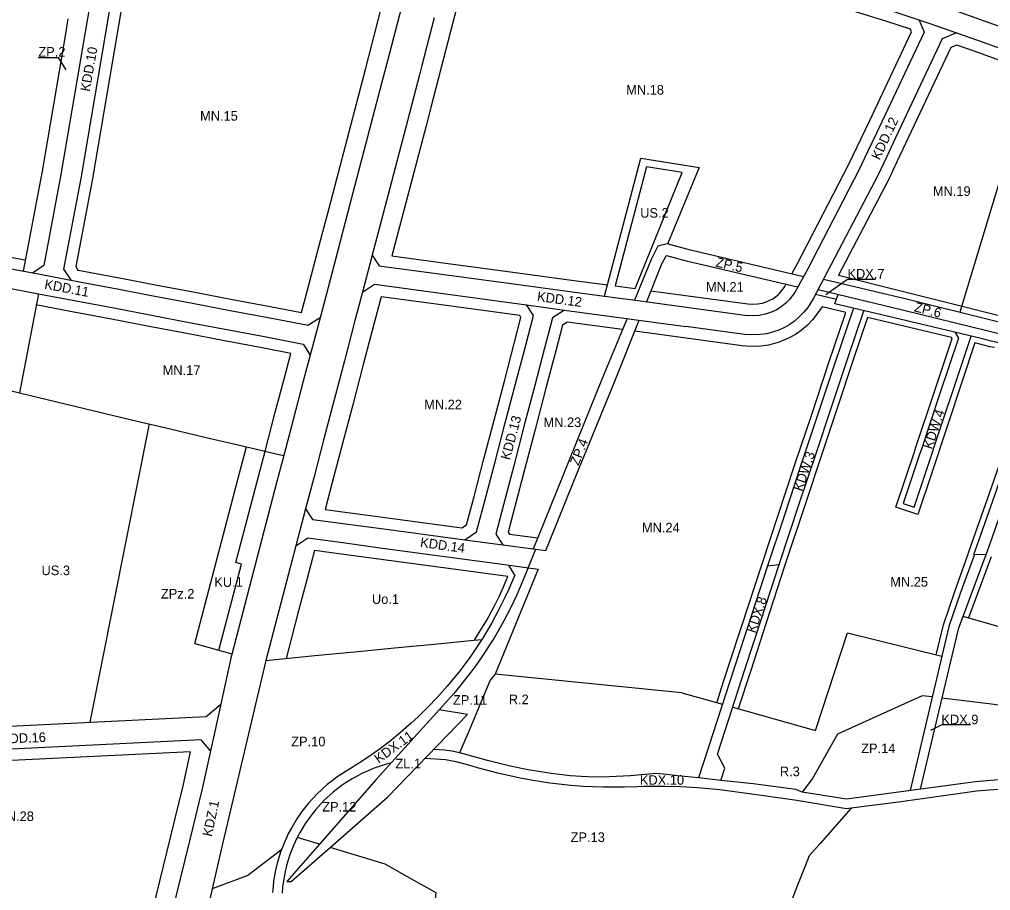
# Model space of a CAD drawing. Extents: x 7416945 to 7418410, y 5548550 to 5549803.
# Drawn here: x 7417372 to 7417879, y 5548828 to 5549282 of the extents above; entities that cross this region are included whole.
import ezdxf

# ---------------------------------------------------------------- set-up
doc = ezdxf.new("R2010")
doc.units = 0
for name, color, linetype in [('linie rozgraniczające', 7, 'Continuous'), ('nieprzekraczalna linia lokalizacyjna', 7, 'Continuous'), ('nieprzekraczalne linie zabudowy', 7, 'Continuous'), ('przeznaczenia terenów', 7, 'Continuous')]:
    doc.layers.add(name, color=color, linetype=linetype)

msp = doc.modelspace()

# ---------------------------------------------------------------- linework, layer by layer
at = {"layer": 'linie rozgraniczające'}
for p, q in [((7417384.22, 5549148.78), (7417364.57, 5549152.5)), ((7417362.71, 5549142.67), (7417382.36, 5549138.96)), ((7417443.16, 5549137.57), (7417423.51, 5549141.29)), ((7417382.36, 5549138.96), (7417372.55, 5549087.23)), ((7417382.36, 5549138.96), (7417402, 5549135.23)), ((7417402, 5549135.23), (7417421.66, 5549131.51)), ((7417462.81, 5549133.84), (7417443.16, 5549137.57)), ((7417482.45, 5549130.09), (7417462.81, 5549133.84)), ((7417502.11, 5549126.37), (7417482.45, 5549130.09)), ((7417523.03, 5549122.41), (7417502.11, 5549126.37)), ((7417529.21, 5549126.31), (7417524.25, 5549123.18)), ((7417460.94, 5549124.01), (7417480.6, 5549120.29)), ((7417480.6, 5549120.29), (7417500.25, 5549116.55)), ((7417524.25, 5549123.18), (7417523.03, 5549122.41)), ((7417500.25, 5549116.55), (7417520.47, 5549112.72)), ((7417520.47, 5549112.72), (7417521.18, 5549111.59)), ((7417440.08, 5549071.07), (7417409.24, 5548915.47)), ((7417637.81, 5548996.07), (7417641.77, 5549005.68)), ((7417643, 5548995.38), (7417620.54, 5548940.54)), ((7417630.78, 5548992.14), (7417627.73, 5548997.43)), ((7417762.54, 5548997.11), (7417768.63, 5548997.71)), ((7417864.45, 5548970.75), (7417980.26, 5548937.76)), ((7417787.49, 5548911.18), (7417804.25, 5548962.09)), ((7417804.25, 5548962.09), (7417853.48, 5548949.9)), ((7417463.99, 5548956.53), (7417483.27, 5548951.15)), ((7417717.79, 5548930.82), (7417620.54, 5548940.54)), ((7417717.79, 5548930.82), (7417739, 5548924.85)), ((7417744.4, 5548923.32), (7417787.49, 5548911.18)), ((7417528.9, 5548851.83), (7417511.9, 5548832.43)), ((7417528.9, 5548851.83), (7417517.33, 5548855.35))]:
    msp.add_line(p, q, dxfattribs=at)
for points in [[(7417600.38, 5549448.11), (7417591.9, 5549387.48), (7417586.15, 5549346.84), (7417584.38, 5549338.73), (7417582.4, 5549329.52), (7417581.1, 5549324.69), (7417570.58, 5549284.41), (7417563.36, 5549256.41)], [(7417420.61, 5549356.86), (7417394.15, 5549201.15), (7417385.15, 5549153.69), (7417379.31, 5549149.71)], [(7417433.7, 5549351.23), (7417429.92, 5549349.03), (7417404.45, 5549199.09), (7417395.47, 5549151.72), (7417399.45, 5549145.87)], [(7417906.81, 5549269.9), (7417851.87, 5549289.57), (7417833.76, 5549295.49), (7417808.87, 5549303.3), (7417795.71, 5549307.92), (7417790.77, 5549308.7), (7417775.81, 5549311.08), (7417756.77, 5549314.1), (7417742.03, 5549316.43), (7417726.22, 5549318.94), (7417710.69, 5549321.4), (7417699, 5549323.26), (7417679.25, 5549326.39), (7417661.44, 5549329.21), (7417642.3, 5549332.24), (7417632.4, 5549333.81), (7417607.94, 5549338.37), (7417603.72, 5549342.84)], [(7418147.34, 5549179.74), (7418143.99, 5549186.16), (7418084.45, 5549204.38), (7418040.68, 5549217.77), (7417983.92, 5549235), (7417952.55, 5549244.38), (7417903.8, 5549259.73), (7417872.26, 5549271.01), (7417847.4, 5549279.75), (7417826.56, 5549286.64), (7417807.47, 5549292.63), (7417790.03, 5549298.09), (7417775.67, 5549301.04), (7417764.12, 5549302.87), (7417752.53, 5549304.72), (7417740.93, 5549306.55), (7417719.26, 5549309.98), (7417700.5, 5549312.94), (7417681.74, 5549315.91), (7417662.97, 5549318.89), (7417638.22, 5549322.81), (7417619.42, 5549325.79), (7417605.57, 5549327.98), (7417599.85, 5549325.25)], [(7417397.8, 5549282.3), (7417396.12, 5549272.43), (7417384.31, 5549202.92), (7417374.39, 5549150.64)], [(7417588.8, 5549282.89), (7417582.37, 5549257.96), (7417581.11, 5549253.1), (7417574.91, 5549229.02), (7417565.67, 5549194.03), (7417556.43, 5549159.04), (7417551.32, 5549139.7), (7417547.25, 5549124.23), (7417541.92, 5549103.92), (7417536.6, 5549083.61), (7417531.27, 5549063.29), (7417525.95, 5549042.97), (7417521.69, 5549026.77), (7417516.61, 5549007.43), (7417512.79, 5548992.92), (7417507.71, 5548973.58), (7417500.89, 5548947.67), (7417492.57, 5548912.33), (7417478.58, 5548852.79), (7417472.9, 5548828.6), (7417470.41, 5548817.08)], [(7417841.59, 5549281.68), (7417844.21, 5549275.29), (7417819.3, 5549222.63), (7417814.75, 5549213.02)], [(7417861.02, 5549274.97), (7417853.66, 5549271.91), (7417829.26, 5549220.17), (7417824.74, 5549210.57)], [(7417902.54, 5549260.18), (7417862.8, 5549129.35)], [(7417563.36, 5549256.41), (7417562.35, 5549252.52), (7417543.61, 5549180.99), (7417538.49, 5549161.56), (7417533.39, 5549142.16), (7417529.21, 5549126.31), (7417524.1, 5549106.95), (7417520.51, 5549093.27), (7417515.4, 5549073.92), (7417510.3, 5549054.58), (7417506.75, 5549041.01), (7417483.36, 5548951.55), (7417482.77, 5548948.86), (7417475.23, 5548914.72), (7417474.34, 5548910.67), (7417467.59, 5548880.07), (7417461.13, 5548853.66), (7417451.56, 5548814.61)], [(7417814.75, 5549213.02), (7417810.21, 5549203.41), (7417783.5, 5549151.85), (7417776.71, 5549139.64), (7417775.64, 5549137.99), (7417773.81, 5549135.71), (7417772.09, 5549133.98), (7417770.41, 5549132.57), (7417768.52, 5549131.26), (7417766.99, 5549130.37), (7417765.02, 5549129.43), (7417761.52, 5549128.24), (7417758.27, 5549127.62), (7417754.82, 5549127.44), (7417751.89, 5549127.66)], [(7417677.49, 5549137.69), (7417696.49, 5549209.65), (7417723.78, 5549205.3), (7417726.83, 5549204.82)], [(7417824.74, 5549210.57), (7417820.21, 5549200.98), (7417786.44, 5549136.31), (7417784.99, 5549134.01), (7417783.52, 5549131.82), (7417781.44, 5549129.24), (7417779.28, 5549127), (7417776.37, 5549124.54), (7417773.86, 5549122.8), (7417771.38, 5549121.38), (7417768.44, 5549120.02), (7417766.23, 5549119.21), (7417763.95, 5549118.54), (7417761.96, 5549118.09), (7417758.66, 5549117.6), (7417753.88, 5549117.46), (7417750.55, 5549117.75), (7417745.51, 5549118.4), (7417719.92, 5549121.87)], [(7417726.83, 5549204.82), (7417710.38, 5549164.86)], [(7417781.26, 5549147.82), (7417722.44, 5549161.63), (7417710.2, 5549164.91), (7417705.42, 5549163.81), (7417701.83, 5549156.79), (7417693.26, 5549135.56)], [(7417556.43, 5549159.04), (7417560.1, 5549153.54), (7417592.59, 5549149.16), (7417612.06, 5549146.53), (7417631.54, 5549143.89), (7417659.51, 5549140.13), (7417677.49, 5549137.69), (7417694.99, 5549135.33), (7417751.89, 5549127.66)], [(7417778.23, 5549142.37), (7417720.98, 5549155.81), (7417710.09, 5549158.73), (7417709.49, 5549158.59), (7417707.29, 5549154.3), (7417699.39, 5549134.74)], [(7417423.51, 5549141.29), (7417403.87, 5549145.03), (7417384.22, 5549148.78)], [(7417791.78, 5549146.54), (7417835.03, 5549136.21), (7417879.03, 5549125.34), (7417899.92, 5549120.14), (7417910.43, 5549117.51)], [(7417551.32, 5549139.7), (7417557.55, 5549143.87), (7417597.18, 5549138.5), (7417636.81, 5549133.12), (7417656.64, 5549130.44), (7417719.92, 5549121.87)], [(7417788.92, 5549141.06), (7417833.61, 5549130.38), (7417877.58, 5549119.52), (7417898.47, 5549114.32), (7417914.41, 5549110.33), (7417943.45, 5549103.3), (7417969.7, 5549096.76), (7417975.19, 5549095.35), (7418012.94, 5549086.32), (7418038.97, 5549081.43), (7418066.78, 5549078.66), (7418089.62, 5549077.64), (7418100.12, 5549081.56)], [(7417798.48, 5549135.9), (7417787.63, 5549138.59)], [(7418054.47, 5549073.19), (7418030.76, 5549077.77), (7418012.99, 5549081.92), (7418002.38, 5549084.6), (7417984.13, 5549088.95), (7417978.23, 5549090.35), (7417967.59, 5549092.55), (7417941.97, 5549099.12), (7417902.4, 5549108.1), (7417892.31, 5549110.78), (7417881.65, 5549113.74), (7417879.1, 5549114.2), (7417874, 5549115.6), (7417870.28, 5549116.48), (7417838.19, 5549124.07), (7417797.73, 5549133.64), (7417799.37, 5549138.56)], [(7417421.66, 5549131.51), (7417441.3, 5549127.75), (7417460.94, 5549124.01)], [(7417604.68, 5549010.56), (7417610.89, 5549014.73), (7417615.15, 5549030.94), (7417620.48, 5549051.25), (7417625.8, 5549071.56), (7417631.13, 5549091.88), (7417636.45, 5549112.19), (7417640.5, 5549127.62), (7417636.81, 5549133.12)], [(7417656.64, 5549130.44), (7417650.41, 5549126.28), (7417646.3, 5549110.63), (7417641.2, 5549091.13), (7417635.57, 5549069.69), (7417630.21, 5549049.23), (7417624.83, 5549028.76), (7417620.82, 5549013.47), (7417624.51, 5549007.95)], [(7417807.36, 5549131.36), (7417797.45, 5549102.13), (7417788.66, 5549075.56), (7417779.73, 5549049.01), (7417771.03, 5549022.44), (7417762.54, 5548997.11), (7417752.05, 5548964.9), (7417750.49, 5548960.16), (7417742.71, 5548936.24), (7417734.17, 5548910.03), (7417726.5, 5548886.43)], [(7417738.22, 5548885.17), (7417740.29, 5548891.52), (7417736.41, 5548898.78), (7417742.39, 5548917.13), (7417750.78, 5548942.92), (7417759.08, 5548968.32), (7417768.63, 5548997.71), (7417779.29, 5549029.94), (7417787.7, 5549055.16), (7417796.02, 5549080.27), (7417804.38, 5549105.4), (7417812.71, 5549130.1)], [(7417689.32, 5549126.01), (7417676.42, 5549094.65), (7417655.91, 5549043.98), (7417643.05, 5549012.22), (7417640.42, 5549005.86)], [(7417646.95, 5549005), (7417648.87, 5549009.69), (7417661.64, 5549041.14), (7417682.54, 5549092.52), (7417695.59, 5549125.17)], [(7417251.28, 5549116.27), (7417275.19, 5549110.54), (7417294.67, 5549105.88), (7417314.13, 5549101.21), (7417333.61, 5549096.55), (7417353.08, 5549091.88), (7417372.55, 5549087.23), (7417392.02, 5549082.56), (7417411.49, 5549077.9), (7417430.97, 5549073.25), (7417450.44, 5549068.58), (7417469.91, 5549063.92), (7417489.41, 5549059.41), (7417506.4, 5549055.48), (7417510.3, 5549054.58)], [(7417860.47, 5549118.8), (7417862.06, 5549115.83), (7417852.26, 5549086.42), (7417842.79, 5549057.95), (7417842.01, 5549055.58), (7417833.32, 5549029.49), (7417839.01, 5549027.6), (7417845.12, 5549045.96), (7417853.34, 5549070.61), (7417861.22, 5549094.32), (7417868.73, 5549116.85)], [(7417521.18, 5549111.59), (7417524.1, 5549106.95)], [(7417917.65, 5549104.64), (7417911.1, 5549101.73), (7417901.89, 5549075.42), (7417890.76, 5549043.69), (7417878.59, 5549008.99), (7417876.3, 5549002.8), (7417870.46, 5549002.86), (7417870.18, 5549002.86), (7417872.8, 5549010.27), (7417881.05, 5549033.88), (7417890.12, 5549059.83), (7417897.87, 5549082.02), (7417905.29, 5549103.25), (7417902.77, 5549108.02)], [(7417473.15, 5548991.58), (7417487.4, 5549046.07), (7417488.27, 5549049.41), (7417488.25, 5549049.41), (7417490.8, 5549059.09)], [(7417521.69, 5549026.77), (7417525.38, 5549021.26), (7417565.03, 5549015.92), (7417604.68, 5549010.56), (7417624.51, 5549007.95), (7417640.42, 5549005.86), (7417641.77, 5549005.68), (7417646.95, 5549005)], [(7417516.61, 5549007.43), (7417522.84, 5549011.59), (7417542.35, 5549008.96), (7417561.83, 5549006.33), (7417581.33, 5549003.7), (7417600.81, 5549001.07), (7417620.29, 5548998.43), (7417643, 5548995.38)], [(7417870.46, 5549002.86), (7417862.99, 5548982.64), (7417857.16, 5548965.46), (7417836.92, 5548879.84)], [(7417876.3, 5549002.8), (7417861.96, 5548964.01), (7417842.23, 5548880.56)], [(7417637.81, 5548996.07), (7417634.66, 5548988.5), (7417631.83, 5548981.98), (7417628.67, 5548975.32), (7417625.03, 5548968.3), (7417622.47, 5548963.71), (7417619.81, 5548959.21), (7417617.47, 5548955.44), (7417615.03, 5548951.69), (7417612.53, 5548948.02), (7417610.39, 5548945), (7417607.91, 5548941.62), (7417604.62, 5548937.37), (7417602.17, 5548934.33), (7417598.97, 5548930.52), (7417594.79, 5548925.81), (7417591.35, 5548921.97)], [(7417463.99, 5548956.53), (7417473.15, 5548991.58)], [(7417630.78, 5548992.14), (7417629.08, 5548988.15), (7417627.63, 5548984.83), (7417625.61, 5548980.45), (7417622.67, 5548974.53), (7417618.75, 5548967.28), (7417613.93, 5548959.2), (7417613.59, 5548958.7), (7417607.31, 5548949.29), (7417602.28, 5548942.49), (7417595.58, 5548934.24), (7417590.35, 5548928.36), (7417585.52, 5548923.3), (7417580.32, 5548918.21), (7417576.78, 5548914.94), (7417571.24, 5548910.11), (7417565.78, 5548905.66), (7417560.69, 5548901.79), (7417556, 5548898.43), (7417552.26, 5548895.89), (7417549.88, 5548894.33), (7417547.52, 5548892.83), (7417546.53, 5548892.21), (7417546.03, 5548891.9), (7417542.29, 5548889.64), (7417540.4, 5548888.44), (7417537.93, 5548886.75), (7417535.49, 5548884.94), (7417532.96, 5548882.92), (7417530.16, 5548880.46), (7417527.71, 5548878.12), (7417523.25, 5548873.28), (7417519.8, 5548868.91), (7417517.13, 5548865.03), (7417514.49, 5548860.65), (7417512.86, 5548857.58), (7417510.8, 5548853.19), (7417508.65, 5548847.65), (7417506.94, 5548842.01), (7417505.89, 5548837.53), (7417505.03, 5548832.51), (7417504.73, 5548830.04), (7417504.44, 5548826.63)], [(7417500.89, 5548947.67), (7417526.52, 5548950.19), (7417547.27, 5548952.21), (7417568, 5548954.24), (7417588.75, 5548956.26), (7417599.01, 5548957.27), (7417609.49, 5548958.3), (7417613.59, 5548958.7)], [(7417620.54, 5548940.54), (7417617.96, 5548937.38), (7417613.08, 5548925.82), (7417606.94, 5548911.17), (7417602.03, 5548899.53)], [(7417848.46, 5548928.64), (7417843.25, 5548929.28), (7417837.74, 5548926.79), (7417799.12, 5548909.3), (7417786.05, 5548886.15), (7417780.56, 5548879)], [(7417946.22, 5548898.97), (7417942.6, 5548900.22), (7417922.04, 5548910.15), (7417889.72, 5548923.38), (7417879.42, 5548924.96), (7417863.45, 5548926.86), (7417853.47, 5548928.11)], [(7417273.67, 5548893.56), (7417278.95, 5548903.58), (7417288.09, 5548909.49), (7417371.16, 5548913.6), (7417469.91, 5548918.46), (7417477.47, 5548924.85)], [(7417534.44, 5548850.15), (7417564.62, 5548876.51), (7417606.08, 5548919.47), (7417591.35, 5548921.97), (7417558.57, 5548885.67), (7417528.9, 5548851.83)], [(7417472.11, 5548900.55), (7417467.24, 5548906.31), (7417371.76, 5548901.6), (7417296.55, 5548897.89)], [(7417885.15, 5548885.64), (7417870.98, 5548884.47), (7417803.72, 5548875.33), (7417780.56, 5548879), (7417777.4, 5548880.44), (7417755, 5548883.36), (7417738.22, 5548885.17), (7417726.58, 5548886.42), (7417715.7, 5548887.6), (7417710.08, 5548888.21), (7417704.57, 5548888.8), (7417690.88, 5548887.46), (7417680.06, 5548887.01), (7417671.53, 5548886.89), (7417668.68, 5548886.93), (7417665.47, 5548887.13), (7417659.67, 5548887.59), (7417649.74, 5548888.68), (7417637.82, 5548890.57), (7417628.34, 5548892.55), (7417616.53, 5548895.48), (7417607.24, 5548898.14), (7417601.27, 5548899.73), (7417597.88, 5548900.33), (7417594.06, 5548900.88), (7417588.5, 5548901.25)], [(7417547.13, 5548886.73), (7417551.61, 5548889.06), (7417554.41, 5548890.34), (7417557.7, 5548891.68), (7417560.82, 5548892.78), (7417564.12, 5548893.79), (7417566.45, 5548894.4)], [(7417806.23, 5548870.62), (7417803.67, 5548870.28), (7417777.91, 5548874.72), (7417759.34, 5548877.34), (7417737.68, 5548880.2), (7417726.01, 5548881.27), (7417717.38, 5548881.76), (7417709.21, 5548882), (7417706.51, 5548882.03), (7417702.57, 5548882.03), (7417698.08, 5548881.97), (7417694.58, 5548881.87), (7417688, 5548881.65), (7417681.8, 5548881.57), (7417677.06, 5548881.61), (7417671.25, 5548881.79), (7417666.67, 5548882.03), (7417660.06, 5548882.52), (7417649.1, 5548883.72), (7417640.32, 5548885.04), (7417633.5, 5548886.28), (7417621.99, 5548888.83), (7417611.27, 5548891.72), (7417606.79, 5548893.09), (7417600.19, 5548894.84), (7417594.69, 5548895.82), (7417583.96, 5548896.55)], [(7417547.13, 5548886.73), (7417545.94, 5548886.01), (7417544.17, 5548884.92), (7417542.78, 5548884.02), (7417540.84, 5548882.68), (7417536.18, 5548879.09), (7417531.25, 5548874.58), (7417527.06, 5548870.03), (7417523.83, 5548865.94), (7417521.33, 5548862.32), (7417518.84, 5548858.19), (7417517.33, 5548855.35), (7417515.4, 5548851.23), (7417513.38, 5548846.01), (7417511.77, 5548840.72), (7417510.79, 5548836.54), (7417509.98, 5548831.79), (7417509.71, 5548829.52), (7417509.44, 5548826.38)], [(7417885.14, 5548880.62), (7417871.53, 5548879.5), (7417844.5, 5548875.74), (7417834.49, 5548874.34), (7417832.16, 5548874.04), (7417806.23, 5548870.62), (7417789.92, 5548852.15), (7417784.27, 5548845.73), (7417782.74, 5548841.85), (7417778.25, 5548830.48), (7417768.76, 5548806.39)], [(7417509.23, 5548849.13), (7417491.62, 5548835.61), (7417472.9, 5548828.6)], [(7417511.9, 5548832.43), (7417514.18, 5548832.45), (7417534.44, 5548850.15)], [(7417570.23, 5548837.5), (7417567.57, 5548838.96), (7417563.23, 5548841.38), (7417534.44, 5548850.15)], [(7417570.23, 5548837.5), (7417589.55, 5548826.76), (7417587.91, 5548810.29), (7417584.76, 5548804.15), (7417543.15, 5548756.83), (7417539.16, 5548752.01), (7417525.02, 5548734.98), (7417512.78, 5548718.47)]]:
    msp.add_lwpolyline(points, dxfattribs=at)
at = {"layer": 'nieprzekraczalna linia lokalizacyjna'}
msp.add_lwpolyline([(7417683.03, 5549143), (7417693.53, 5549141.58), (7417718, 5549202.17), (7417699.43, 5549205.13), (7417683.03, 5549143)], dxfattribs=at)
at = {"layer": 'nieprzekraczalne linie zabudowy'}
for points in [[(7417434.88, 5549342.36), (7417410.35, 5549198.03), (7417401.82, 5549153.05), (7417403.01, 5549151.3), (7417404.99, 5549150.92), (7417424.63, 5549147.18), (7417444.28, 5549143.47), (7417463.93, 5549139.73), (7417483.57, 5549135.98), (7417503.23, 5549132.27), (7417519.62, 5549129.16), (7417523.72, 5549144.71), (7417528.82, 5549164.11), (7417533.94, 5549183.53), (7417553.08, 5549256.59), (7417560.91, 5549286.92), (7417570.83, 5549324.94), (7417562.97, 5549325.95), (7417544.48, 5549328.32), (7417525.98, 5549330.69), (7417507.49, 5549333.06), (7417487.5, 5549335.62), (7417434.88, 5549342.36)], [(7417609.16, 5549321.34), (7417598.48, 5549280.38), (7417587.05, 5549236.07), (7417584.59, 5549226.5), (7417566.68, 5549158.71), (7417593.39, 5549155.11), (7417612.86, 5549152.48), (7417632.34, 5549149.84), (7417660.31, 5549146.08), (7417679.03, 5549143.54)], [(7417280.75, 5549300.59), (7417278.75, 5549283.32), (7417276.73, 5549271.22), (7417267.63, 5549218.08), (7417264.16, 5549195.55), (7417262.15, 5549179.79), (7417263.67, 5549177.71), (7417287.09, 5549173.26), (7417326.39, 5549165.83), (7417346.03, 5549162.1), (7417365.68, 5549158.4), (7417375.51, 5549156.54)], [(7417775.19, 5549149.25), (7417778.21, 5549154.69), (7417804.83, 5549206.07), (7417809.33, 5549215.58), (7417815.66, 5549228.96), (7417837.66, 5549275.46), (7417837.09, 5549276.84), (7417824.72, 5549280.93), (7417805.68, 5549286.9)], [(7417799.6, 5549148.55), (7417830.66, 5549140.78), (7417908.42, 5549121.35), (7417923.1, 5549171.81), (7417929.47, 5549193.7), (7417939.89, 5549229.5), (7417923.27, 5549234.73), (7417926.71, 5549246.23), (7417901.89, 5549254.04), (7417870.25, 5549265.36), (7417861.19, 5549268.54), (7417858.1, 5549267.26), (7417830.16, 5549208.01), (7417825.59, 5549198.31), (7417799.6, 5549148.55)], [(7417701.71, 5549140.47), (7417752.34, 5549133.64), (7417754.89, 5549133.45), (7417757.55, 5549133.59), (7417759.99, 5549134.05), (7417762.75, 5549134.99), (7417764.19, 5549135.68), (7417765.3, 5549136.33), (7417766.77, 5549137.35), (7417768.03, 5549138.4), (7417769.33, 5549139.71), (7417770.77, 5549141.51), (7417771.56, 5549142.74), (7417772.15, 5549143.8)], [(7417561.04, 5549137.34), (7417556.92, 5549121.69), (7417551.59, 5549101.38), (7417546.27, 5549081.07), (7417540.94, 5549060.76), (7417535.62, 5549040.43), (7417531.94, 5549026.43), (7417565.83, 5549021.87), (7417603.23, 5549016.81), (7417605.66, 5549018.45), (7417609.35, 5549032.46), (7417614.68, 5549052.77), (7417620, 5549073.08), (7417625.33, 5549093.4), (7417630.65, 5549113.71), (7417634.01, 5549126.53), (7417633.33, 5549127.54), (7417596.37, 5549132.55), (7417561.04, 5549137.34)], [(7417476.53, 5548953.08), (7417488.27, 5548997.99), (7417485.36, 5548998.74), (7417497.08, 5549043.54), (7417500.55, 5549056.83), (7417500.55, 5549056.83), (7417505.73, 5549076.47), (7417510.84, 5549095.82), (7417513.99, 5549107.84), (7417499.13, 5549110.66), (7417479.48, 5549114.4), (7417459.82, 5549118.12), (7417440.17, 5549121.86), (7417420.54, 5549125.62), (7417400.88, 5549129.33), (7417381.07, 5549133.1)], [(7417736.11, 5548925.66), (7417739.86, 5548937.17), (7417747.64, 5548961.09), (7417749.2, 5548965.83), (7417759.69, 5548998.05), (7417768.18, 5549023.38), (7417776.88, 5549049.95), (7417785.81, 5549076.51), (7417794.61, 5549103.08), (7417803.46, 5549129.2), (7417790.97, 5549132.16), (7417788.35, 5549128.26), (7417785.94, 5549125.26), (7417783.38, 5549122.62), (7417780.02, 5549119.77), (7417777.06, 5549117.73), (7417774.14, 5549116.05), (7417770.75, 5549114.48), (7417768.12, 5549113.51), (7417765.46, 5549112.73), (7417763.06, 5549112.18), (7417759.18, 5549111.61), (7417753.72, 5549111.45), (7417749.35, 5549111.83), (7417693.29, 5549119.42)], [(7417880.98, 5549110.81), (7417878.44, 5549111.27), (7417873.26, 5549112.69), (7417870.71, 5549113.3), (7417864.07, 5549093.37), (7417856.19, 5549069.66), (7417847.97, 5549045.01), (7417840.91, 5549023.81), (7417829.52, 5549027.59), (7417839.16, 5549056.52), (7417839.94, 5549058.89), (7417849.41, 5549087.37), (7417858.81, 5549115.55), (7417858.47, 5549116.19), (7417814.68, 5549126.55), (7417807.22, 5549104.45), (7417798.87, 5549079.32), (7417790.55, 5549054.21), (7417782.14, 5549028.99), (7417771.48, 5548996.78), (7417761.93, 5548967.39), (7417753.63, 5548941.99), (7417747.29, 5548922.51)], [(7417686.96, 5549120.28), (7417658.08, 5549124.19), (7417655.64, 5549122.55), (7417652.1, 5549109.11), (7417647, 5549089.61), (7417641.37, 5549068.17), (7417636.01, 5549047.71), (7417630.63, 5549027.24), (7417627.31, 5549014.56), (7417627.99, 5549013.54), (7417642.79, 5549011.6)], [(7417850.57, 5548950.62), (7417854.28, 5548966.29), (7417860.16, 5548983.64), (7417865.94, 5548999.86), (7417869.97, 5549011.26), (7417878.22, 5549034.87), (7417887.29, 5549060.82)], [(7417609.73, 5548958.32), (7417611.39, 5548960.8), (7417616.14, 5548968.77), (7417620, 5548975.91), (7417622.9, 5548981.75), (7417624.9, 5548986.06), (7417626.33, 5548989.33), (7417627.22, 5548991.44), (7417600.01, 5548995.12), (7417580.53, 5548997.75), (7417561.03, 5549000.38), (7417541.55, 5549003.01), (7417526.33, 5549005.07), (7417522.46, 5548990.38), (7417517.38, 5548971.04), (7417511.51, 5548948.71)], [(7417879.11, 5549001.76), (7417867.35, 5548969.92)], [(7417441.31, 5548814.81), (7417441.85, 5548816.99), (7417451.42, 5548856.04), (7417457.85, 5548882.34), (7417461.75, 5548900.04), (7417372.05, 5548895.61), (7417298.16, 5548891.96), (7417293.26, 5548889.42), (7417290.97, 5548884.14), (7417292.69, 5548828.47), (7417292.73, 5548826.87), (7417301.25, 5548827.4), (7417301.53, 5548818.39)]]:
    msp.add_lwpolyline(points, dxfattribs=at)
at = {"layer": 'przeznaczenia terenów'}
for points in [[(7417382.32, 5549262.13), (7417392.75, 5549262.13), (7417396.69, 5549255.68)], [(7417818.77, 5549146.43), (7417804.24, 5549146.43), (7417793.04, 5549138.42)], [(7417868.43, 5548914.08), (7417853.43, 5548914.08), (7417847.49, 5548911.08)]]:
    msp.add_lwpolyline(points, dxfattribs=at)

# ---------------------------------------------------------------- texts
for s, p in [('ZP.2', (7417382.36, 5549262.6)), ('MN.18', (7417688.86, 5549242.8)), ('MN.15', (7417466.68, 5549229.19)), ('MN.19', (7417848.75, 5549189.94)), ('US.2', (7417696.16, 5549178.59)), ('KDX.7', (7417804.23, 5549146.87)), ('MN.21', (7417730.47, 5549139.99)), ('MN.17', (7417447.17, 5549096.53)), ('MN.22', (7417583.53, 5549078.67)), ('MN.23', (7417645.72, 5549069.39)), ('MN.24', (7417697.08, 5549014.46)), ('US.3', (7417384, 5548992.18)), ('KU.1', (7417474.09, 5548986.09)), ('MN.25', (7417826.53, 5548986.2)), ('ZPz.2', (7417446.26, 5548979.99)), ('Uo.1', (7417556.3, 5548977.19)), ('ZP.11', (7417598.54, 5548924.59)), ('R.2', (7417627.65, 5548924.89)), ('KDX.9', (7417853.2, 5548914.42)), ('ZP.10', (7417514.21, 5548902.92)), ('ZP.14', (7417811.4, 5548899.36)), ('ZL.1', (7417568.53, 5548891.39)), ('R.3', (7417768.99, 5548887.31)), ('ZP.12', (7417530.35, 5548868.9)), ('MN.28', (7417360.34, 5548863.98)), ('ZP.13', (7417659.89, 5548853.02))]:
    msp.add_text(s, height=5, dxfattribs=at).set_placement(p)
for s, rotation, p in [('KDD.10', 79.8982, (7417409.11, 5549244.13)), ('KDD.12', 64.7058, (7417820.96, 5549208.31)), ('ZP.5', 347.0883, (7417735.23, 5549153.17)), ('KDD.11', 349.1992, (7417385.23, 5549141.61)), ('KDD.12', 352.1474, (7417642.19, 5549135.2)), ('ZP.6', 345.7424, (7417838.73, 5549129.8)), ('KDD.13', 75.1238, (7417628.22, 5549051.92)), ('KDW.4', 71.5003, (7417848.3, 5549057.48)), ('ZP.4', 68.4276, (7417663.98, 5549048.97)), ('KDW.3', 71.408, (7417780.66, 5549035.54)), ('KDD.14', 352.1474, (7417581.23, 5549006.95)), ('KDX.8', 71.3577, (7417756.2, 5548961.6)), ('KDD.16', 2.2573, (7417362.96, 5548904.3)), ('KDX.11', 35.9598, (7417559.81, 5548893.8)), ('KDX.10', 0.0926, (7417696.01, 5548882.83)), ('KDZ.1', 78.0712, (7417472.78, 5548855.55))]:
    msp.add_text(s, height=5, rotation=rotation, dxfattribs=at).set_placement(p)

doc.saveas('drawing.dxf')
